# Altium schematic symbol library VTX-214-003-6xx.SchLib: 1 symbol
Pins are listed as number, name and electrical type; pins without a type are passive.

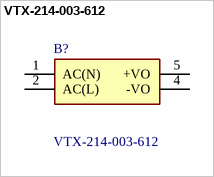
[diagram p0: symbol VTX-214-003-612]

## VTX-214-003-612
designator B?
AC/DC PCB Mount Power Supply (PSU), Class II, ITE & Household, 1 Output, 3 W, 12 VDC, 250 mA; Manufacturer_Name: VIGORTRONIX; Geometry.Height: 17.65mm
footprint VTX214003612
pins: 1 AC(N), 2 AC(L), 4 -VO, 5 +VO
